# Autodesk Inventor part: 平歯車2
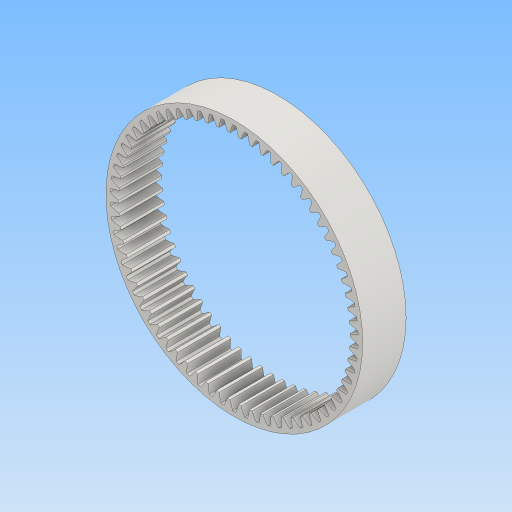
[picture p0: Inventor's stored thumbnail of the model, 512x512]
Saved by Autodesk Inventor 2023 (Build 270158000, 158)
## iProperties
CustomPartVersion: 1
Created: 2024-01
Part Number: 平歯車2
Material: Steel
Document SubType Name: Modeling
Designer: kumagai
Categories: <?xml version="1.0" encoding="UTF-16"?> <MemberInstance><Categories><FamilyTemplate><FamilyTemplateParameter ValueType="xs:double" Id="1" ObjectReferenceKey="da
Density: 1 g/cm^3
Appearance: Steel
Author: kumagai
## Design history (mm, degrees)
sketch "Sketch1"
  geometry: C1 r 35.5 at (0, 0)
  constraints: 1 centre point
  dimensions: "d0" = 71 diameter of C1
extrude "Extrusion1" new body sketch "Sketch1" distance "d1" = 12 (= da_b); taper "d2" = 0 deg
workplane "Work Plane2"
sketch "Sketch2"
  geometry: C1 r 35.5 at (0, 0) reference; C2 r 33 at (0, 0)
  constraints: 1 centre point, 1 coincident
  dimensions: "d3" = 66 diameter of C2 (= da_d)
feature "ピッチ円直径" sketch "Sketch2" dims "d4" = 10, "d5" = 0
workplane "Work Plane8"
workplane "Work Plane9"
feature "平歯車" dims "da_b" = 12, "da_d" = 66, "da_z" = 660, "da_aw" = 22, "da_da" = 64, "da_df" = 68.5, "da_dw" = 66, "da_z2" = 220, "da_beta" = 0, "da_lefttooth" = 0, "da_righttooth" = 0, "da_straighttooth" = 10
body "Solid1"
body "Srf1"
other parameters: "d16" = 22 (= da_aw), "d17" = 0, "d34" = 0.476 (computed from da_z), "d39" = 0, "d45" = 0, "d47" = 22 (= da_aw), "d50" = 0, "d51" = 0, "d52" = 22 (= da_aw)
